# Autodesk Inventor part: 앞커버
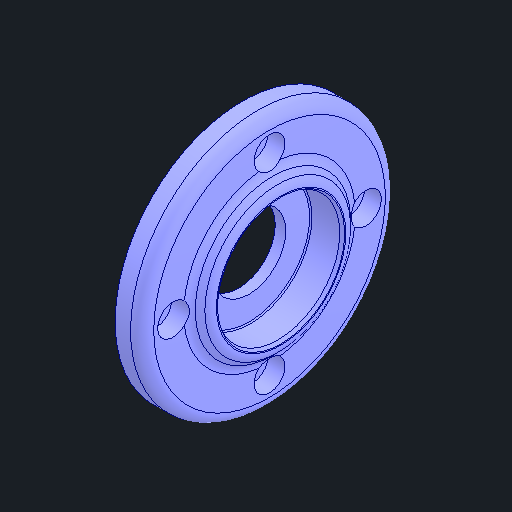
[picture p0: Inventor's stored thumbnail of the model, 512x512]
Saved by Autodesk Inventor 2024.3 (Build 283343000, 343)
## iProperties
Created: 2025-05
Part Number: 앞커버
Material: 알루미늄 6061
Document SubType Name: Modeling
Designer: user
Density: 2.7 g/cm^3
Appearance: 기본값
Author: jhkim
Sending System: Autodesk Inventor 2026
Preprocessor: ST-DEVELOPER v20.1
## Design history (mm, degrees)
feature "솔리드1"
node "솔리드2"
